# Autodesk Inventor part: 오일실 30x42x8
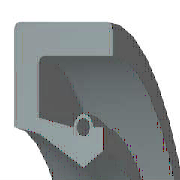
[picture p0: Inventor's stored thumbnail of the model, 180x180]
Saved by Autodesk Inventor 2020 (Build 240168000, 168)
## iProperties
Created: 2009-02
Part Number: 오일실 30x42x8
Material: 고무
Document SubType Name: Modeling
Standard: KS B 2804
Designer: mdu
Standards Organization: KS
Language: ko-KR
Size Designation: S - 30 42 8
Categories: <MemberInstance><Categories><Category DisplayName="샤프트 부품" InternalName="7f7aeb1f-a693-4053-b835-cee3144e0d98" Mnemonic="SHFT"><Category DisplayName="실링" Intern
Density: 0.93 g/cm^3
Appearance: 고무 - 검은색 - 버전 1.1
IsCustomPart: 0
Author: mdu
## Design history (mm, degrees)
revolve "본체" stored, may be unused: angle "d17" = 90 deg
revolve "스프링1" stored, may be unused: angle "d18" = 90 deg
body "Solid1"
sketch "스케치1"
  geometry: L1 (0, 21)-(8, 21); L2 (8, 21)-(8, 19.75); L3 (8, 19.75)-(1.75, 19.75); L4 (0, 21)-(0, 17.1); L5 (0, 17.1)-(1.75, 16.75); L6 (1.75, 16.75)-(4.9, 15); L7 (4.9, 15)-(0, 15); L8 (6.3, 15.875)-(6.3, 17.1); L9 (0, 0)-(9.586, 0) reference; L10 (4.9, 15)-(6.3, 15.875); L11 (0, 18)-(0, -3) reference; L12 (-1.917, 0)-(11.503, 0) reference; L13 (4.2, 17.1)-(1.75, 17.59); L14 (1.75, 17.59)-(1.75, 19.75); L15 (6.3, 17.1)-(5.6, 17.1); C1 r 0.455 at (4.9, 17.1); A1 r 0.7 centre (4.9, 17.1) between (5.6, 17.1) and (4.2, 17.1)
  constraints: 26 end point, 5 horizontal alignment, 4 perpendicular, 2 centre point, 2 collinear, 2 horizontal, 2 parallel, 2 point on circle, 2 point on line, 2 vertical alignment, 1 coincident
  dimensions: "d0" = 42 diameter of L1 L9 (= SD2); "d1" = 31.75 diameter of L8.start L9 (= ABDM); "d2" = 1.25 distance of L1.end L2.end (computed from SD); "d3" = 0.91 diameter of C1 (= SPDI); "d4" = 1.4 diameter of A1 (= SPDA); "d5" = 30 diameter of L6.end L9 (= NND); "d6" = 33.5 diameter of L5.end L9 (= TKDM); "d7" = 34.2 diameter of L4.end L9 (= HLDM); "d8" = 4.9 distance from line of C1.centre L4 (= SPDST); "d9" = 6.3 distance between parallel lines of L8 L4 (= SDI); "d10" = 8 distance between parallel lines of L2 L4 (= SWDT); "d12" = 1.75 distance between parallel lines of L14 L4 (= SD)
fillet "모깎기1" dims "d11" = 0.4 (= RR)
other parameters: "SD2" = 42 [user parameter; used in 1 equation term], "SWDT" = 8 [user parameter; used in 1 equation term], "RR" = 0.4 [user parameter; used in 1 equation term], "SD" = 1.75 [user parameter; used in 2 equation terms], "NND" = 30 [user parameter; used in 1 equation term], "SPDA" = 1.4 [user parameter; used in 1 equation term], "SPDI" = 0.91 [user parameter; used in 1 equation term], "TKDM" = 33.5 [user parameter; used in 1 equation term], "HLDM" = 34.2 [user parameter; used in 1 equation term], "ABDM" = 31.75 [user parameter; used in 1 equation term], "SDI" = 6.3 [user parameter; used in 1 equation term], "SPDST" = 4.9 [user parameter; used in 1 equation term], "d13" = 0, "d14" = 0, "d15" = 0, "LAB" = 0.35 [user parameter]
